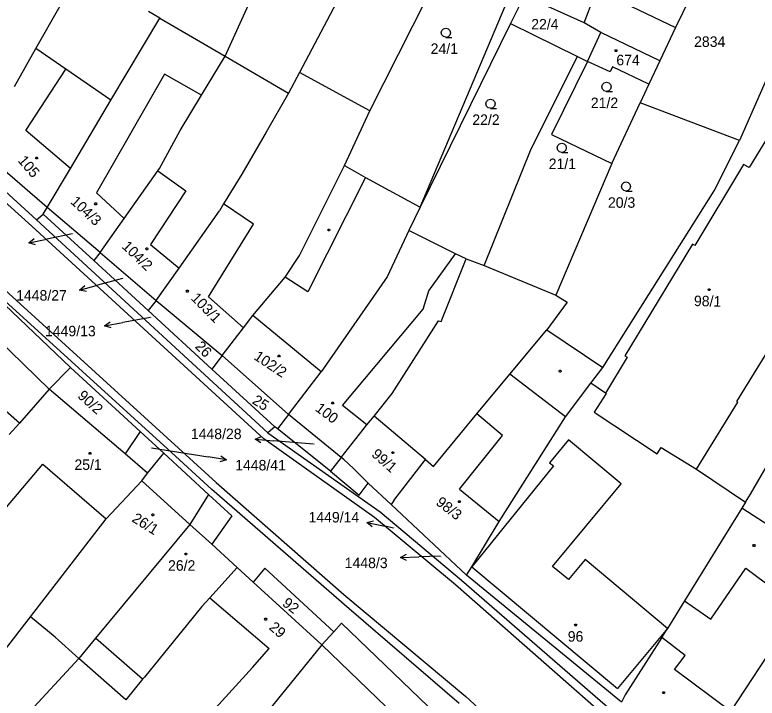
# Model space of a CAD drawing. Extents: x -580630 to -576196, y -1189024 to -1183567.
# Drawn here: x -578693.1 to -578572.8, y -1185883.6 to -1185773 of the extents above; entities that cross this region are included whole.
import ezdxf

# ---------------------------------------------------------------- set-up
doc = ezdxf.new("R2010")
doc.units = 0
for name, color, linetype in [('Vrstva 1', 7, 'Continuous'), ('Vrstva 16', 7, 'Continuous'), ('Vrstva 18', 7, 'Continuous'), ('Vrstva 19', 7, 'Continuous'), ('Vrstva 25', 7, 'Continuous'), ('Vrstva 4', 7, 'Continuous')]:
    doc.layers.add(name, color=color, linetype=linetype)

msp = doc.modelspace()

# ---------------------------------------------------------------- linework, layer by layer
at = {"layer": 'Vrstva 1'}
for p, q in [((-578659.02, -1185779.69), (-578644.45, -1185747.6)), ((-578635.55, -1185788.53), (-578615.84, -1185749.43)), ((-578639.2, -1185767.61), (-578646.94, -1185782.35)), ((-578582.25, -1185767.27), (-578586.06, -1185775.04)), ((-578627.42, -1185804.13), (-578612.54, -1185768.95)), ((-578600.83, -1185774.31), (-578598.83, -1185768.88)), ((-578610.54, -1185769.9), (-578612.79, -1185774.4)), ((-578600.83, -1185774.31), (-578610.54, -1185769.9)), ((-578689.66, -1185778.46), (-578685.74, -1185771.55)), ((-578669.6, -1185773.54), (-578671.42, -1185772.46)), ((-578677.51, -1185786.84), (-578669.6, -1185773.54)), ((-578669.6, -1185773.54), (-578659.02, -1185779.69)), ((-578567.05, -1185773.59), (-578575.67, -1185793.35)), ((-578612.79, -1185774.4), (-578627.42, -1185804.13)), ((-578612.79, -1185774.4), (-578601.92, -1185779.74)), ((-578598.13, -1185775.85), (-578600.83, -1185774.31)), ((-578600.32, -1185780.53), (-578598.13, -1185775.85)), ((-578588.61, -1185780.44), (-578598.13, -1185775.85)), ((-578586.06, -1185775.04), (-578588.61, -1185780.44)), ((-578693.15, -1185784.61), (-578689.66, -1185778.46)), ((-578684.79, -1185781.82), (-578689.66, -1185778.46)), ((-578662.83, -1185785.99), (-578659.02, -1185779.69)), ((-578659.02, -1185779.69), (-578648.75, -1185785.67)), ((-578609.46, -1185794.72), (-578601.92, -1185779.74)), ((-578601.92, -1185779.74), (-578600.32, -1185780.53)), ((-578600.32, -1185780.53), (-578606.16, -1185792.38)), ((-578596.66, -1185782.22), (-578600.32, -1185780.53)), ((-578588.61, -1185780.44), (-578590.39, -1185784.22)), ((-578677.51, -1185786.84), (-578684.79, -1185781.82)), ((-578596.29, -1185781.44), (-578596.66, -1185782.22)), ((-578590.39, -1185784.22), (-578596.29, -1185781.44)), ((-578646.94, -1185782.35), (-578648.75, -1185785.67)), ((-578635.55, -1185788.53), (-578646.94, -1185782.35)), ((-578590.39, -1185784.22), (-578591.81, -1185787.27)), ((-578648.75, -1185785.67), (-578652.36, -1185791.98)), ((-578684.07, -1185797.88), (-578677.51, -1185786.84)), ((-578666.29, -1185791.72), (-578662.83, -1185785.99)), ((-578596.38, -1185797.09), (-578591.81, -1185787.27)), ((-578575.67, -1185793.35), (-578591.81, -1185787.27)), ((-578690.31, -1185807.22), (-578711.13, -1185788.55)), ((-578639.69, -1185797.42), (-578635.55, -1185788.53)), ((-578669.66, -1185797.89), (-578666.29, -1185791.72)), ((-578569.91, -1185790.76), (-578574.11, -1185797.74)), ((-578652.36, -1185791.98), (-578656.32, -1185798.82)), ((-578606.16, -1185792.38), (-578596.38, -1185797.09)), ((-578579.82, -1185801.47), (-578575.67, -1185793.35)), ((-578687.84, -1185804.22), (-578698.87, -1185794.67)), ((-578617.08, -1185813.57), (-578609.46, -1185794.72)), ((-578700.25, -1185796.44), (-578689.54, -1185806.21)), ((-578687.84, -1185804.22), (-578684.07, -1185797.88)), ((-578646.94, -1185811.99), (-578639.69, -1185797.42)), ((-578639.69, -1185797.42), (-578636.26, -1185799.34)), ((-578596.38, -1185797.09), (-578605.43, -1185818.38)), ((-578575.03, -1185797.22), (-578582.94, -1185810.34)), ((-578574.11, -1185797.74), (-578575.03, -1185797.22)), ((-578675.36, -1185805.96), (-578669.93, -1185798.28)), ((-578669.93, -1185798.28), (-578669.66, -1185797.89)), ((-578656.32, -1185798.82), (-578659.26, -1185803.61)), ((-578636.26, -1185799.34), (-578627.42, -1185804.13)), ((-578713.52, -1185800.41), (-578660.46, -1185848.7)), ((-578597.85, -1185830.1), (-578579.82, -1185801.47)), ((-578659.26, -1185803.61), (-578659.94, -1185804.72)), ((-578668.35, -1185843.29), (-578711.68, -1185803.9)), ((-578684.04, -1185830.1), (-578711.68, -1185803.9)), ((-578688.47, -1185805.28), (-578687.84, -1185804.22)), ((-578679.26, -1185811.48), (-578687.84, -1185804.22)), ((-578666.48, -1185814.02), (-578659.94, -1185804.72)), ((-578627.42, -1185804.13), (-578629.28, -1185807.91)), ((-578689.54, -1185806.21), (-578688.47, -1185805.28)), ((-578689.54, -1185806.21), (-578652.07, -1185840.68)), ((-578688.47, -1185805.28), (-578680.3, -1185812.78)), ((-578679.26, -1185811.48), (-578675.36, -1185805.96)), ((-578652.75, -1185841.65), (-578690.31, -1185807.22)), ((-578629.28, -1185807.91), (-578632.77, -1185815.44)), ((-578621.68, -1185811.67), (-578629.28, -1185807.91)), ((-578583.32, -1185810.11), (-578594.27, -1185828.2)), ((-578582.94, -1185810.34), (-578583.32, -1185810.11)), ((-578679.26, -1185811.48), (-578680.3, -1185812.78)), ((-578679.26, -1185811.48), (-578670.17, -1185819.26)), ((-578649.29, -1185815.48), (-578646.94, -1185811.99)), ((-578619.96, -1185812.52), (-578621.68, -1185811.67)), ((-578680.3, -1185812.78), (-578671.46, -1185820.89)), ((-578624.01, -1185822.67), (-578619.96, -1185812.52)), ((-578619.96, -1185812.52), (-578617.08, -1185813.57)), ((-578670.17, -1185819.26), (-578666.48, -1185814.02)), ((-578617.08, -1185813.57), (-578605.43, -1185818.38)), ((-578654.51, -1185821.66), (-578649.29, -1185815.48)), ((-578632.77, -1185815.44), (-578643.45, -1185830.82)), ((-578576.12, -1185835.63), (-578564.07, -1185815.93)), ((-578670.17, -1185819.26), (-578671.46, -1185820.89)), ((-578670.17, -1185819.26), (-578659.47, -1185828.14)), ((-578603.59, -1185819.52), (-578606.89, -1185824.03)), ((-578605.43, -1185818.38), (-578603.59, -1185819.52)), ((-578701.22, -1185820.29), (-578687.52, -1185833.62)), ((-578671.46, -1185820.89), (-578661.14, -1185830.36)), ((-578656.06, -1185823.69), (-578654.51, -1185821.66)), ((-578631.96, -1185834.3), (-578624.47, -1185822.54)), ((-578624.47, -1185822.54), (-578624.01, -1185822.67)), ((-578573.89, -1185850.62), (-578557.76, -1185822.49)), ((-578659.47, -1185828.14), (-578656.06, -1185823.69)), ((-578612.9, -1185831.2), (-578606.89, -1185824.03)), ((-578606.89, -1185824.03), (-578597.85, -1185830.1)), ((-578659.47, -1185828.14), (-578661.14, -1185830.36)), ((-578659.47, -1185828.14), (-578648.74, -1185837.73)), ((-578593.89, -1185828.43), (-578597.41, -1185834.25)), ((-578594.27, -1185828.2), (-578593.89, -1185828.43)), ((-578687.52, -1185833.62), (-578684.04, -1185830.1)), ((-578684.04, -1185830.1), (-578672.76, -1185840.47)), ((-578599.76, -1185832.62), (-578597.85, -1185830.1)), ((-578661.14, -1185830.36), (-578650.95, -1185839.71)), ((-578648.74, -1185837.73), (-578643.45, -1185830.82)), ((-578618.25, -1185837.58), (-578612.9, -1185831.2)), ((-578603.89, -1185838.07), (-578599.76, -1185832.62)), ((-578597.41, -1185834.25), (-578599.76, -1185832.62)), ((-578687.52, -1185833.62), (-578692.34, -1185839.12)), ((-578675.23, -1185844.08), (-578687.52, -1185833.62)), ((-578634.89, -1185837.96), (-578631.96, -1185834.3)), ((-578597.28, -1185834.33), (-578599.21, -1185837.33)), ((-578597.41, -1185834.25), (-578597.28, -1185834.33)), ((-578582.66, -1185846.58), (-578575.99, -1185835.71)), ((-578575.99, -1185835.71), (-578576.12, -1185835.63)), ((-578599.21, -1185837.33), (-578589.04, -1185844.08)), ((-578648.74, -1185837.73), (-578650.54, -1185840.04)), ((-578640.24, -1185844.67), (-578648.74, -1185837.73)), ((-578636.04, -1185839.4), (-578634.89, -1185837.96)), ((-578625.27, -1185846.12), (-578618.25, -1185837.58)), ((-578614.65, -1185855.02), (-578603.89, -1185838.07)), ((-578692.34, -1185839.12), (-578693.98, -1185840.96)), ((-578650.95, -1185839.71), (-578652.07, -1185840.68)), ((-578650.54, -1185840.04), (-578650.95, -1185839.71)), ((-578640.24, -1185844.67), (-578636.04, -1185839.4)), ((-578672.76, -1185840.47), (-578675.23, -1185844.08)), ((-578668.93, -1185844), (-578672.76, -1185840.47)), ((-578652.07, -1185840.68), (-578633.92, -1185853.47)), ((-578641.94, -1185846.91), (-578650.54, -1185840.04)), ((-578634.84, -1185854.4), (-578652.75, -1185841.65)), ((-578661.15, -1185849.84), (-578668.35, -1185843.29)), ((-578589.04, -1185844.08), (-578588.41, -1185843.05)), ((-578588.41, -1185843.05), (-578582.66, -1185846.58)), ((-578671.57, -1185847.19), (-578675.23, -1185844.08)), ((-578671.57, -1185847.19), (-578668.93, -1185844)), ((-578668.93, -1185844), (-578661.68, -1185850.68)), ((-578640.24, -1185844.67), (-578641.94, -1185846.91)), ((-578631.69, -1185851.65), (-578626.57, -1185844.98)), ((-578626.57, -1185844.98), (-578625.27, -1185846.12)), ((-578641.94, -1185846.91), (-578637.3, -1185850.79)), ((-578582.66, -1185846.58), (-578574.71, -1185851.91)), ((-578672.49, -1185848.43), (-578671.57, -1185847.19)), ((-578678.28, -1185854.63), (-578672.49, -1185848.43)), ((-578660.46, -1185848.7), (-578639.79, -1185866.86)), ((-578637.3, -1185850.79), (-578635.82, -1185848.82)), ((-578632.13, -1185852.28), (-578635.82, -1185848.82)), ((-578661.68, -1185850.68), (-578664.72, -1185855.5)), ((-578661.68, -1185850.68), (-578657.94, -1185854.12)), ((-578638.92, -1185869.17), (-578661.15, -1185849.84)), ((-578574.71, -1185851.91), (-578573.89, -1185850.62)), ((-578631.69, -1185851.65), (-578632.13, -1185852.28)), ((-578574.71, -1185851.91), (-578575.31, -1185852.88)), ((-578619.89, -1185863.72), (-578632.13, -1185852.28)), ((-578575.31, -1185852.88), (-578579.34, -1185859.39)), ((-578563.04, -1185860.88), (-578575.31, -1185852.88)), ((-578657.94, -1185854.12), (-578661.18, -1185858.73)), ((-578633.92, -1185853.47), (-578620.73, -1185864.55)), ((-578690.52, -1185870.46), (-578678.28, -1185854.63)), ((-578664.72, -1185855.5), (-578680.02, -1185873.95)), ((-578621.7, -1185865.32), (-578634.84, -1185854.4)), ((-578619.07, -1185862.4), (-578614.65, -1185855.02)), ((-578657.05, -1185862.48), (-578661.18, -1185858.73)), ((-578579.34, -1185859.39), (-578584.59, -1185867.89)), ((-578657.05, -1185862.48), (-578661.5, -1185867.4)), ((-578654.46, -1185864.86), (-578657.05, -1185862.48)), ((-578652.58, -1185862.62), (-578654.46, -1185864.86)), ((-578641.4, -1185872.88), (-578652.58, -1185862.62)), ((-578619.89, -1185863.72), (-578619.07, -1185862.4)), ((-578594.83, -1185884.3), (-578619.89, -1185863.72)), ((-578643.36, -1185875.02), (-578654.46, -1185864.86)), ((-578620.73, -1185864.55), (-578594.05, -1185887.66)), ((-578594.79, -1185888.89), (-578621.7, -1185865.32)), ((-578661.5, -1185867.4), (-578662.76, -1185868.8)), ((-578639.79, -1185866.86), (-578620.03, -1185883.37)), ((-578662.76, -1185868.8), (-578672.08, -1185880.22)), ((-578584.59, -1185867.89), (-578587.34, -1185872.34)), ((-578621.11, -1185884.52), (-578638.92, -1185869.17)), ((-578577.1, -1185885.8), (-578566.01, -1185868.83)), ((-578694.74, -1185875.91), (-578690.52, -1185870.46)), ((-578686.56, -1185873.75), (-578690.52, -1185870.46)), ((-578641.4, -1185872.88), (-578640.15, -1185871.52)), ((-578640.15, -1185871.52), (-578626.11, -1185884.98)), ((-578588.27, -1185873.82), (-578587.34, -1185872.34)), ((-578643.36, -1185875.02), (-578641.4, -1185872.88)), ((-578682.73, -1185877.22), (-578686.56, -1185873.75)), ((-578680.02, -1185873.95), (-578682.73, -1185877.22)), ((-578588.27, -1185873.82), (-578594.23, -1185883.12)), ((-578643.36, -1185875.02), (-578656.98, -1185891.78)), ((-578698.48, -1185894.24), (-578682.73, -1185877.22)), ((-578675.1, -1185883.91), (-578682.73, -1185877.22)), ((-578672.38, -1185880.58), (-578675.1, -1185883.91)), ((-578672.08, -1185880.22), (-578672.38, -1185880.58)), ((-578594.23, -1185883.12), (-578594.83, -1185884.3)), ((-578620.03, -1185883.37), (-578607.87, -1185894.4))]:
    msp.add_line(p, q, dxfattribs=at)
at = {"layer": 'Vrstva 16'}
for p, q in [((-578683.71, -1185808.48), (-578687.89, -1185809.33)), ((-578690.829, -1185809.93), (-578687.89, -1185809.33)), ((-578675.66, -1185815.71), (-578679.68, -1185816.79)), ((-578682.577, -1185817.568), (-578679.68, -1185816.79)), ((-578678.552, -1185823.352), (-578675.6, -1185822.82)), ((-578671.12, -1185822.01), (-578675.6, -1185822.82)), ((-578654.159, -1185841.7), (-578651.17, -1185841.96)), ((-578644.72, -1185842.52), (-578651.17, -1185841.96)), ((-578670.94, -1185843.12), (-578661.74, -1185844.59)), ((-578658.778, -1185845.066), (-578661.74, -1185844.59)), ((-578636.044, -1185855.195), (-578633.11, -1185855.82)), ((-578631.76, -1185856.11), (-578633.11, -1185855.82)), ((-578630.628, -1185860.891), (-578627.63, -1185860.77)), ((-578624.2, -1185860.63), (-578627.63, -1185860.77))]:
    msp.add_line(p, q, dxfattribs=at)
for points in [[(-578689.75, -1185810.22), (-578690.829, -1185809.93), (-578689.95, -1185809.24)], [(-578681.482, -1185817.791), (-578682.577, -1185817.568), (-578681.741, -1185816.826)], [(-578677.48, -1185823.667), (-578678.552, -1185823.352), (-578677.657, -1185822.682)], [(-578653.206, -1185842.285), (-578654.159, -1185841.7), (-578653.119, -1185841.289)], [(-578659.686, -1185844.414), (-578658.778, -1185845.066), (-578659.845, -1185845.401)], [(-578635.17, -1185855.893), (-578636.044, -1185855.195), (-578634.962, -1185854.914)], [(-578629.608, -1185861.35), (-578630.628, -1185860.891), (-578629.648, -1185860.351)]]:
    msp.add_lwpolyline(points, dxfattribs=at)
at = {"layer": 'Vrstva 25'}
for points in [[(-578623.25, -1185776.63), (-578623.63, -1185776.53), (-578623.9, -1185776.26), (-578624, -1185775.89), (-578623.9, -1185775.52), (-578623.63, -1185775.25), (-578623.26, -1185775.15), (-578622.89, -1185775.25), (-578622.62, -1185775.52), (-578622.52, -1185775.9), (-578622.62, -1185776.28), (-578622.89, -1185776.55), (-578623.27, -1185776.65), (-578622.27, -1185776.65)], [(-578597.23, -1185785.4), (-578597.61, -1185785.3), (-578597.88, -1185785.03), (-578597.98, -1185784.66), (-578597.88, -1185784.29), (-578597.61, -1185784.02), (-578597.24, -1185783.92), (-578596.87, -1185784.02), (-578596.6, -1185784.29), (-578596.5, -1185784.67), (-578596.6, -1185785.05), (-578596.87, -1185785.32), (-578597.25, -1185785.42), (-578596.25, -1185785.42)], [(-578616.01, -1185788.13), (-578616.39, -1185788.03), (-578616.66, -1185787.76), (-578616.76, -1185787.39), (-578616.66, -1185787.02), (-578616.39, -1185786.75), (-578616.02, -1185786.65), (-578615.65, -1185786.75), (-578615.38, -1185787.02), (-578615.28, -1185787.4), (-578615.38, -1185787.78), (-578615.65, -1185788.05), (-578616.03, -1185788.15), (-578615.03, -1185788.15)], [(-578604.48, -1185795.27), (-578604.86, -1185795.17), (-578605.13, -1185794.9), (-578605.23, -1185794.53), (-578605.13, -1185794.16), (-578604.86, -1185793.89), (-578604.49, -1185793.79), (-578604.12, -1185793.89), (-578603.85, -1185794.16), (-578603.75, -1185794.54), (-578603.85, -1185794.92), (-578604.12, -1185795.19), (-578604.5, -1185795.29), (-578603.5, -1185795.29)], [(-578594.07, -1185801.54), (-578594.45, -1185801.44), (-578594.72, -1185801.17), (-578594.82, -1185800.8), (-578594.72, -1185800.43), (-578594.45, -1185800.16), (-578594.08, -1185800.06), (-578593.71, -1185800.16), (-578593.44, -1185800.43), (-578593.34, -1185800.81), (-578593.44, -1185801.19), (-578593.71, -1185801.46), (-578594.09, -1185801.56), (-578593.09, -1185801.56)]]:
    msp.add_lwpolyline(points, dxfattribs=at)
for points in [[(-578595.6, -1185778.66), (-578595.51, -1185778.81), (-578595.6, -1185778.96), (-578595.78, -1185778.96), (-578595.87, -1185778.81), (-578595.78, -1185778.66)], [(-578689.44, -1185796.02), (-578689.35, -1185796.17), (-578689.44, -1185796.32), (-578689.62, -1185796.32), (-578689.71, -1185796.17), (-578689.62, -1185796.02)], [(-578679.91, -1185803.46), (-578679.82, -1185803.61), (-578679.91, -1185803.76), (-578680.09, -1185803.76), (-578680.18, -1185803.61), (-578680.09, -1185803.46)], [(-578642.12, -1185807.69), (-578642.03, -1185807.84), (-578642.12, -1185807.99), (-578642.3, -1185807.99), (-578642.39, -1185807.84), (-578642.3, -1185807.69)], [(-578671.6, -1185810.75), (-578671.51, -1185810.9), (-578671.6, -1185811.05), (-578671.78, -1185811.05), (-578671.87, -1185810.9), (-578671.78, -1185810.75)], [(-578665.03, -1185817.59), (-578664.94, -1185817.74), (-578665.03, -1185817.89), (-578665.21, -1185817.89), (-578665.3, -1185817.74), (-578665.21, -1185817.59)], [(-578580.51, -1185817.36), (-578580.42, -1185817.51), (-578580.51, -1185817.66), (-578580.69, -1185817.66), (-578580.78, -1185817.51), (-578580.69, -1185817.36)], [(-578650.2, -1185828.08), (-578650.11, -1185828.23), (-578650.2, -1185828.38), (-578650.38, -1185828.38), (-578650.47, -1185828.23), (-578650.38, -1185828.08)], [(-578604.66, -1185830.55), (-578604.57, -1185830.7), (-578604.66, -1185830.85), (-578604.84, -1185830.85), (-578604.93, -1185830.7), (-578604.84, -1185830.55)], [(-578641.5, -1185835.69), (-578641.41, -1185835.84), (-578641.5, -1185835.99), (-578641.68, -1185835.99), (-578641.77, -1185835.84), (-578641.68, -1185835.69)], [(-578680.82, -1185843.84), (-578680.73, -1185843.99), (-578680.82, -1185844.14), (-578681, -1185844.14), (-578681.09, -1185843.99), (-578681, -1185843.84)], [(-578631.76, -1185843.74), (-578631.67, -1185843.89), (-578631.76, -1185844.04), (-578631.94, -1185844.04), (-578632.03, -1185843.89), (-578631.94, -1185843.74)], [(-578620.99, -1185851.68), (-578620.9, -1185851.83), (-578620.99, -1185851.98), (-578621.17, -1185851.98), (-578621.26, -1185851.83), (-578621.17, -1185851.68)], [(-578670.64, -1185853.82), (-578670.55, -1185853.97), (-578670.64, -1185854.12), (-578670.82, -1185854.12), (-578670.91, -1185853.97), (-578670.82, -1185853.82)], [(-578573.24, -1185858.78), (-578573.15, -1185858.93), (-578573.24, -1185859.08), (-578573.42, -1185859.08), (-578573.51, -1185858.93), (-578573.42, -1185858.78)], [(-578665.28, -1185860.16), (-578665.19, -1185860.31), (-578665.28, -1185860.46), (-578665.46, -1185860.46), (-578665.55, -1185860.31), (-578665.46, -1185860.16)], [(-578652.36, -1185870.71), (-578652.27, -1185870.86), (-578652.36, -1185871.01), (-578652.54, -1185871.01), (-578652.63, -1185870.86), (-578652.54, -1185870.71)], [(-578602.16, -1185871.65), (-578602.07, -1185871.8), (-578602.16, -1185871.95), (-578602.34, -1185871.95), (-578602.43, -1185871.8), (-578602.34, -1185871.65)], [(-578587.9, -1185882.61), (-578587.81, -1185882.76), (-578587.9, -1185882.91), (-578588.08, -1185882.91), (-578588.17, -1185882.76), (-578588.08, -1185882.61)]]:
    msp.add_lwpolyline(points, close=True, dxfattribs=at)
at = {"layer": 'Vrstva 4'}
for p, q in [((-578595.66, -1185770.43), (-578586.06, -1185775.04)), ((-578691.31, -1185791.7), (-578684.79, -1185781.82)), ((-578668.81, -1185782.62), (-578679.84, -1185801.8)), ((-578662.83, -1185785.99), (-578668.81, -1185782.62)), ((-578684.07, -1185797.88), (-578691.31, -1185791.7)), ((-578669.93, -1185798.28), (-578665.4, -1185801.47)), ((-578636.26, -1185799.34), (-578645.62, -1185817.84)), ((-578665.4, -1185801.47), (-578671.11, -1185810.21)), ((-578679.84, -1185801.8), (-578675.36, -1185805.96)), ((-578654.44, -1185806.89), (-578659.26, -1185803.61)), ((-578661.68, -1185818.68), (-578654.44, -1185806.89)), ((-578671.11, -1185810.21), (-578666.48, -1185814.02)), ((-578626, -1185817.69), (-578621.68, -1185811.67)), ((-578645.62, -1185817.84), (-578649.29, -1185815.48)), ((-578626.91, -1185820.67), (-578626, -1185817.69)), ((-578656.06, -1185823.69), (-578661.68, -1185818.68)), ((-578640, -1185836.23), (-578626.91, -1185820.67)), ((-578643.45, -1185830.82), (-578654.51, -1185821.66)), ((-578692.34, -1185839.12), (-578706.39, -1185826.74)), ((-578603.89, -1185838.07), (-578612.9, -1185831.2)), ((-578636.04, -1185839.4), (-578640, -1185836.23)), ((-578626.57, -1185844.98), (-578634.89, -1185837.96)), ((-578614.06, -1185841.09), (-578618.25, -1185837.58)), ((-578621.07, -1185849.79), (-578614.06, -1185841.09)), ((-578603.37, -1185841.83), (-578606.45, -1185845.52)), ((-578594.85, -1185848.95), (-578603.37, -1185841.83)), ((-578639.76, -1185845.01), (-578640.24, -1185844.67)), ((-578698.3, -1185857.27), (-578688.54, -1185845.78)), ((-578688.54, -1185845.78), (-578678.28, -1185854.63)), ((-578638.21, -1185846.48), (-578639.76, -1185845.01)), ((-578606.45, -1185845.52), (-578605.83, -1185846.03)), ((-578635.82, -1185848.82), (-578638.21, -1185846.48)), ((-578605.83, -1185846.03), (-578619.07, -1185862.4)), ((-578664.72, -1185855.5), (-578672.49, -1185848.43)), ((-578605.99, -1185862.31), (-578594.85, -1185848.95)), ((-578621.07, -1185849.79), (-578614.65, -1185855.02)), ((-578661.18, -1185858.73), (-578664.72, -1185855.5)), ((-578600.7, -1185861.19), (-578603.42, -1185864.45)), ((-578587.34, -1185872.34), (-578600.7, -1185861.19)), ((-578619.07, -1185862.4), (-578595.48, -1185882.09)), ((-578603.42, -1185864.45), (-578605.99, -1185862.31)), ((-578580.34, -1185870.88), (-578574.65, -1185862.6)), ((-578574.65, -1185862.6), (-578567.64, -1185867.87)), ((-578661.5, -1185867.4), (-578651.89, -1185875.6)), ((-578584.59, -1185867.89), (-578580.34, -1185870.88)), ((-578587.34, -1185872.34), (-578595.48, -1185882.09)), ((-578672.38, -1185880.58), (-578680.02, -1185873.95)), ((-578584.48, -1185876.75), (-578588.27, -1185873.82)), ((-578654.57, -1185878.67), (-578651.89, -1185875.6)), ((-578643.36, -1185875.02), (-578629.28, -1185888.52)), ((-578586.21, -1185878.99), (-578584.48, -1185876.75)), ((-578662.98, -1185887.87), (-578654.57, -1185878.67)), ((-578577.1, -1185885.8), (-578586.21, -1185878.99))]:
    msp.add_line(p, q, dxfattribs=at)

# ---------------------------------------------------------------- texts
at = {"layer": 'Vrstva 16'}
for s, p in [('1448/27', (-578692.866, -1185819.27)), ('1449/13', (-578688.193, -1185825.05)), ('1448/28', (-578664.566, -1185841.7)), ('1448/41', (-578657.387, -1185846.77)), ('1449/14', (-578645.509, -1185855.2)), ('1448/3', (-578639.644, -1185862.59))]:
    msp.add_text(s, height=1.7, dxfattribs=at).set_placement(p)
at = {"layer": 'Vrstva 18'}
for s, height, p in [('22/4', 1.7, (-578609.431, -1185775.37)), ('2834', 1.7, (-578583.051, -1185778.19)), ('24/1', 1.7, (-578625.719, -1185779.33)), ('21/2', 1.7, (-578599.773, -1185788.1)), ('22/2', 1.7, (-578618.975, -1185790.83)), ('21/1', 1.7, (-578606.601, -1185797.97)), ('20/3', 1.7, (-578597.001, -1185804.24)), ('29/2', 0.1, (-578683.88, -1185808.48)), ('1448/27', 0.1, (-578675.926, -1185815.71)), ('1449/13', 0.1, (-578671.367, -1185822.01)), ('1448/41', 0.1, (-578671.184, -1185843.12)), ('1448/28', 0.1, (-578644.99, -1185842.52)), ('1449/14', 0.1, (-578632.002, -1185856.11))]:
    msp.add_text(s, height=height, dxfattribs=at).set_placement(p)
for s, height, rotation, p in [('26', 1.7, 314.15276, (-578663.992, -1185826.8)), ('90/2', 1.7, 317.99158, (-578683.033, -1185834.867)), ('25', 1.7, 327.38808, (-578654.757, -1185835.833)), ('1448/3', 0.1, 323.1482, (-578624.333, -1185860.583)), ('92', 1.7, 322.74713, (-578649.885, -1185868.55))]:
    msp.add_text(s, height=height, rotation=rotation, dxfattribs=at).set_placement(p)
at = {"layer": 'Vrstva 19'}
for s, p in [('674', (-578595.644, -1185781.17)), ('25/1', (-578683.426, -1185846.69)), ('26/2', (-578668.261, -1185863.01)), ('96', (-578603.515, -1185874.5))]:
    msp.add_text(s, height=1.7, dxfattribs=at).set_placement(p)
for s, rotation, p in [('105', 310.71501, (-578692.676, -1185796.657)), ('104/3', 316.84566, (-578684.184, -1185803.392)), ('104/2', 316.04352, (-578675.853, -1185810.629)), ('103/1', 314.55383, (-578664.67, -1185818.978)), ('98/1', 358.55699, (-578583.092, -1185820.149)), ('102/2', 326.47135, (-578654.497, -1185828.68)), ('100', 322.97631, (-578644.545, -1185837.001)), ('99/1', 318.85101, (-578635.434, -1185844.344)), ('98/3', 322.05958, (-578624.994, -1185852.203)), ('26/1', 328.19023, (-578674.249, -1185854.958)), ('29', 318.79372, (-578652.027, -1185872.368))]:
    msp.add_text(s, height=1.7, rotation=rotation, dxfattribs=at).set_placement(p)

doc.saveas('drawing.dxf')
